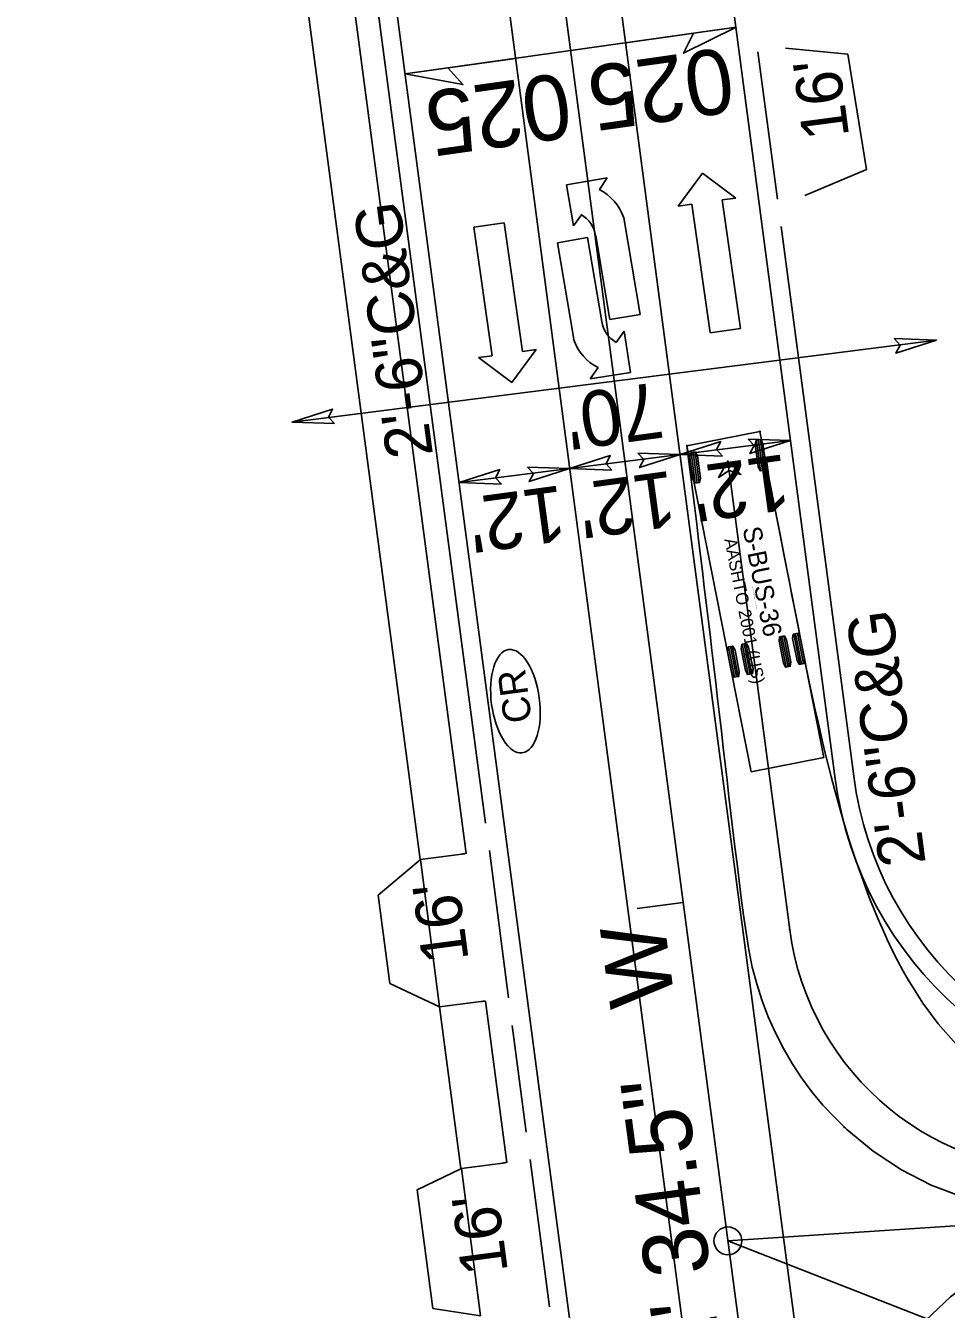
# Model space of a CAD drawing. Extents: x 2367848 to 2369479, y 800728 to 808616.
# Drawn here: x 2368550.2 to 2368649.4, y 806072.5 to 806210.8 of the extents above; entities that cross this region are included whole.
import ezdxf

# ---------------------------------------------------------------- set-up
doc = ezdxf.new("R2010")
doc.units = 0
for name, color, linetype in [('Prop AutoTurn Projected Path', 7, 'Continuous'), ('Prop AutoTurn Simulation', 7, 'Continuous'), ('Prop Conc 2ft 6in Curb and Gutter', 7, 'Continuous'), ('Prop Conc 4in Sidewalk', 7, 'Continuous'), ('Prop Conc Drive Radius Type', 7, 'Continuous'), ('Prop Conc Driveway', 7, 'Continuous'), ('Prop Dimension', 7, 'Continuous'), ('Prop EOT', 7, 'Continuous'), ('Prop Horizontal Alignment', 7, 'Continuous'), ('Prop Horizontal Alignment Direction Label', 7, 'Continuous'), ('Prop Horizontal Alignment Station Label', 7, 'Continuous'), ('Prop Horizontal Alignment Tick Small', 7, 'Continuous'), ('Prop Lane Arrow CELL', 7, 'Continuous'), ('Prop Lane Lines', 7, 'Continuous'), ('Prop Shade Light', 7, 'Continuous'), ('Prop Superelevation  Arrow CELL', 7, 'Continuous'), ('Prop Superelevation Label', 7, 'Continuous'), ('Prop Terminator CELL', 7, 'Continuous'), ('Prop WCC CELL', 7, 'Continuous'), ('Prop WCR CELL', 7, 'Continuous')]:
    doc.layers.add(name, color=color, linetype=linetype)

# ---------------------------------------------------------------- blocks, each defined once
blk = doc.blocks.new('CR')
at = {"layer": 'Prop WCC CELL'}
blk.add_ellipse((0.02, -0.02), major_axis=(5.61, 0), ratio=0.462467, dxfattribs=at)
blk.add_text('CR', height=3, dxfattribs=at).set_placement((-2.34, -1.5))

msp = doc.modelspace()

# ---------------------------------------------------------------- linework, layer by layer
at = {"layer": 'Prop AutoTurn Projected Path'}
msp.add_line((2368632.53, 806113.4), (2368625.87, 806163.88), dxfattribs=at)
for centre, radius, start, end in [((2368662.28, 806117.33), 30, 187.5263, 273.7494), ((2368673.73, 806045.93), 32, 93.7494, 187.5296)]:
    msp.add_arc(centre, radius, start, end, dxfattribs=at)
at = {"layer": 'Prop AutoTurn Simulation'}
for p, q in [((2368629.31, 806167.1), (2368621.46, 806165.56)), ((2368636.22, 806131.97), (2368629.31, 806167.1)), ((2368621.46, 806165.56), (2368628.37, 806130.43)), ((2368621.46, 806165.56), (2368621.46, 806165.56)), ((2368628.96, 806166.17), (2368629.4, 806162.86)), ((2368629.17, 806166.19), (2368629.6, 806162.89)), ((2368629.38, 806166.22), (2368629.81, 806162.92)), ((2368621.92, 806164.83), (2368622.36, 806161.53)), ((2368622.13, 806164.86), (2368622.56, 806161.56)), ((2368622.33, 806164.89), (2368622.77, 806161.58)), ((2368631.5, 806144.97), (2368632.14, 806141.7)), ((2368631.7, 806145.01), (2368632.35, 806141.74)), ((2368631.91, 806145.05), (2368632.55, 806141.78)), ((2368632.97, 806145.26), (2368633.61, 806141.99)), ((2368633.17, 806145.3), (2368633.82, 806142.03)), ((2368633.38, 806145.34), (2368634.02, 806142.07)), ((2368625.94, 806143.88), (2368626.58, 806140.61)), ((2368626.14, 806143.92), (2368626.79, 806140.65)), ((2368626.35, 806143.96), (2368626.99, 806140.69)), ((2368627.41, 806144.17), (2368628.05, 806140.9)), ((2368627.61, 806144.21), (2368628.26, 806140.94)), ((2368627.82, 806144.25), (2368628.46, 806140.98)), ((2368628.37, 806130.43), (2368636.22, 806131.97))]:
    msp.add_line(p, q, dxfattribs=at)
for points in [[(2368645.29, 806108), (2368644.77, 806108.92), (2368644.16, 806110.07), (2368643.58, 806111.21), (2368643.03, 806112.35), (2368642.52, 806113.49), (2368642.03, 806114.62), (2368641.56, 806115.75), (2368641.11, 806116.87), (2368640.69, 806117.98), (2368640.29, 806119.09), (2368639.9, 806120.19), (2368639.53, 806121.28), (2368639.17, 806122.38), (2368638.81, 806123.52), (2368638.45, 806124.71), (2368638.09, 806125.95), (2368637.72, 806127.24), (2368637.36, 806128.56), (2368637, 806129.92), (2368636.65, 806131.3), (2368636.3, 806132.72), (2368635.96, 806134.16), (2368635.62, 806135.62), (2368635.29, 806137.1), (2368634.96, 806138.6), (2368634.64, 806140.12), (2368634.32, 806141.65), (2368634.01, 806143.19), (2368633.71, 806144.75), (2368633.4, 806146.31), (2368633.09, 806147.88), (2368632.78, 806149.45), (2368632.47, 806151.04), (2368632.16, 806152.63), (2368631.84, 806154.22), (2368631.53, 806155.82), (2368631.21, 806157.42), (2368630.9, 806159.03), (2368630.58, 806160.64), (2368630.26, 806162.25), (2368629.94, 806163.86), (2368629.63, 806165.48), (2368629.31, 806167.1)], [(2368638.43, 806092.11), (2368637.38, 806093.15), (2368636.12, 806094.51), (2368634.93, 806095.94), (2368633.82, 806097.44), (2368632.8, 806098.99), (2368631.85, 806100.61), (2368630.99, 806102.28), (2368630.23, 806104), (2368629.55, 806105.75), (2368628.98, 806107.55), (2368628.5, 806109.38), (2368628.12, 806111.23), (2368627.83, 806113.1), (2368627.57, 806114.97), (2368627.32, 806116.83), (2368627.09, 806118.67), (2368626.86, 806120.5), (2368626.63, 806122.32), (2368626.41, 806124.14), (2368626.2, 806125.94), (2368625.99, 806127.73), (2368625.78, 806129.51), (2368625.58, 806131.28), (2368625.37, 806133.04), (2368625.17, 806134.8), (2368624.96, 806136.54), (2368624.76, 806138.29), (2368624.56, 806140.02), (2368624.35, 806141.75), (2368624.15, 806143.48), (2368623.95, 806145.2), (2368623.74, 806146.91), (2368623.54, 806148.62), (2368623.33, 806150.33), (2368623.13, 806152.03), (2368622.92, 806153.73), (2368622.71, 806155.43), (2368622.51, 806157.12), (2368622.3, 806158.81), (2368622.09, 806160.5), (2368621.88, 806162.19), (2368621.67, 806163.87), (2368621.46, 806165.56)], [(2368650.43, 806101.09), (2368648.52, 806103.25), (2368646.87, 806105.49), (2368645.43, 806107.78), (2368645.29, 806108)], [(2368651.12, 806084.62), (2368647.79, 806085.88), (2368644.58, 806087.52), (2368641.53, 806089.52), (2368638.7, 806091.86), (2368638.43, 806092.11)], [(2368647.18, 806071.28), (2368649.86, 806073.83), (2368652.8, 806076.09), (2368655.96, 806078.06), (2368659.32, 806079.7), (2368662.84, 806080.99), (2368666.48, 806081.91), (2368668.71, 806082.29)]]:
    msp.add_lwpolyline(points, dxfattribs=at)
for points in [[(2368628.91, 806166.16), (2368629.43, 806166.23), (2368629.64, 806165.79), (2368629.96, 806163.41), (2368629.86, 806162.92), (2368629.35, 806162.85), (2368629.13, 806163.3), (2368628.82, 806165.68)], [(2368621.87, 806164.83), (2368622.38, 806164.9), (2368622.6, 806164.45), (2368622.92, 806162.07), (2368622.82, 806161.59), (2368622.31, 806161.52), (2368622.09, 806161.96), (2368621.77, 806164.34)], [(2368625.87, 806163.88), (2368624.87, 806162.14), (2368626, 806162.88), (2368627.28, 806162.46)], [(2368631.45, 806144.96), (2368631.96, 806145.06), (2368632.2, 806144.64), (2368632.66, 806142.28), (2368632.6, 806141.79), (2368632.09, 806141.69), (2368631.85, 806142.12), (2368631.38, 806144.48)], [(2368632.92, 806145.25), (2368633.43, 806145.35), (2368633.67, 806144.93), (2368634.14, 806142.57), (2368634.07, 806142.08), (2368633.56, 806141.98), (2368633.32, 806142.41), (2368632.85, 806144.77)], [(2368625.89, 806143.87), (2368626.4, 806143.97), (2368626.64, 806143.54), (2368627.1, 806141.19), (2368627.04, 806140.7), (2368626.53, 806140.6), (2368626.29, 806141.03), (2368625.82, 806143.38)], [(2368627.36, 806144.16), (2368627.87, 806144.26), (2368628.11, 806143.83), (2368628.58, 806141.48), (2368628.51, 806140.99), (2368628, 806140.89), (2368627.76, 806141.32), (2368627.29, 806143.67)]]:
    msp.add_lwpolyline(points, close=True, dxfattribs=at)
for centre in [(2368629.31, 806167.1), (2368621.46, 806165.56), (2368625.87, 806163.88), (2368632.53, 806113.4), (2368632.53, 806113.4), (2368645.29, 806108), (2368645.29, 806108), (2368638.43, 806092.11), (2368638.43, 806092.11)]:
    msp.add_circle(centre, 0.0417, dxfattribs=at)
at = {"layer": 'Prop Conc 2ft 6in Curb and Gutter'}
for p, q in [((2368599.75, 806124.89), (2368582.79, 806253.21)), ((2368639.43, 806129.93), (2368631.6, 806189.19)), ((2368604.15, 806091.59), (2368602.63, 806103.08))]:
    msp.add_line(p, q, dxfattribs=at)
msp.add_arc((2368677.1, 806134.91), 38, 187.5263, 269.9974, dxfattribs=at)
at = {"layer": 'Prop Conc 4in Sidewalk'}
for p, q in [((2368597.66, 806121.63), (2368579.93, 806255.81)), ((2368592.7, 806120.96), (2368574.97, 806255.2)), ((2368597.1, 806087.65), (2368594.8, 806105.09)), ((2368602.06, 806088.33), (2368599.76, 806105.69))]:
    msp.add_line(p, q, dxfattribs=at)
for centre, radius, start, end in [((2368596.82, 806124.52), 3, 277.425, 286.2491), ((2368599.64, 806102.68), 3.01, 87.5978, 97.1636), ((2368601.22, 806091.22), 3, 277.4254, 286.1541)]:
    msp.add_arc(centre, radius, start, end, dxfattribs=at)
at = {"layer": 'Prop Conc Drive Radius Type'}
for p, q in [((2368629.11, 806208), (2368631.21, 806192.14)), ((2368602.24, 806106.06), (2368600.18, 806121.92)), ((2368606.64, 806072.76), (2368604.58, 806088.62))]:
    msp.add_line(p, q, dxfattribs=at)
at = {"layer": 'Prop Conc Driveway'}
for p, q in [((2368592.74, 806120.96), (2368597.2, 806121.54)), ((2368588.19, 806117.14), (2368592.74, 806120.96)), ((2368594.8, 806105.09), (2368592.74, 806120.96)), ((2368589.43, 806107.62), (2368588.19, 806117.14)), ((2368594.8, 806105.09), (2368589.43, 806107.62)), ((2368594.8, 806105.09), (2368599.26, 806105.67)), ((2368601.61, 806088.24), (2368597.15, 806087.66)), ((2368597.15, 806087.66), (2368592.4, 806085.38)), ((2368599.2, 806071.79), (2368597.15, 806087.66)), ((2368594.06, 806072.59), (2368592.4, 806085.38)), ((2368599.2, 806071.79), (2368594.06, 806072.59))]:
    msp.add_line(p, q, dxfattribs=at)
at = {"layer": 'Prop Dimension'}
for p, q in [((2368578.91, 806168.11), (2368648.35, 806176.94)), ((2368596.92, 806161.58), (2368632.63, 806166.12))]:
    msp.add_line(p, q, dxfattribs=at)
at = {"layer": 'Prop EOT'}
for p, q in [((2368613.33, 806037.35), (2368557.45, 806460.31)), ((2368637.45, 806129.67), (2368615.22, 806297.92)), ((2368638.8, 806207.75), (2368632.09, 806208.39)), ((2368640.8, 806195.31), (2368638.8, 806207.75)), ((2368634.18, 806192.53), (2368640.8, 806195.31))]:
    msp.add_line(p, q, dxfattribs=at)
msp.add_arc((2368677.1, 806134.91), 40, 187.5263, 269.9974, dxfattribs=at)
at = {"layer": 'Prop Horizontal Alignment'}
for p, q in [((2368631.17, 806039.71), (2368556.15, 806607.59)), ((2368625.87, 806079.87), (2368847.64, 806094.4))]:
    msp.add_line(p, q, dxfattribs=at)
at = {"layer": 'Prop Horizontal Alignment Station Label'}
msp.add_line((2368625.87, 806079.87), (2368713.66, 806045.49), dxfattribs=at)
msp.add_circle((2368625.87, 806079.87), 1.5, dxfattribs=at)
at = {"layer": 'Prop Horizontal Alignment Tick Small'}
msp.add_line((2368621.05, 806116.34), (2368616.09, 806115.69), dxfattribs=at)
at = {"layer": 'Prop Lane Arrow CELL'}
for p, q in [((2368620.51, 806191.37), (2368623.14, 806194.93)), ((2368623.14, 806194.93), (2368626.74, 806192.25)), ((2368612.87, 806194.42), (2368608.48, 806193.68)), ((2368608.48, 806193.68), (2368609.23, 806189.24)), ((2368612.02, 806193.16), (2368612.87, 806194.42)), ((2368626.74, 806192.25), (2368625.26, 806192.04)), ((2368625.26, 806192.04), (2368627.22, 806178.18)), ((2368609.23, 806189.24), (2368610.09, 806190.45)), ((2368621.99, 806191.58), (2368620.51, 806191.37)), ((2368623.95, 806177.72), (2368621.99, 806191.58)), ((2368598.51, 806189.12), (2368601.78, 806189.58)), ((2368600.46, 806175.26), (2368598.51, 806189.12)), ((2368601.78, 806189.58), (2368603.73, 806175.72)), ((2368616.41, 806179.7), (2368614.66, 806190.11)), ((2368610.76, 806187.98), (2368607.51, 806187.43)), ((2368612.28, 806178.95), (2368610.76, 806187.98)), ((2368611.64, 806188.18), (2368613.16, 806179.15)), ((2368607.51, 806187.43), (2368609.26, 806177.03)), ((2368613.16, 806179.15), (2368616.41, 806179.7)), ((2368627.22, 806178.18), (2368623.95, 806177.72)), ((2368614.69, 806177.89), (2368613.83, 806176.68)), ((2368615.39, 806173.44), (2368614.69, 806177.89)), ((2368598.98, 806175.05), (2368600.46, 806175.26)), ((2368605.22, 806175.93), (2368602.59, 806172.37)), ((2368603.73, 806175.72), (2368605.22, 806175.93)), ((2368602.59, 806172.37), (2368598.98, 806175.05)), ((2368611.9, 806173.97), (2368611.04, 806172.76)), ((2368611.04, 806172.76), (2368615.39, 806173.44))]:
    msp.add_line(p, q, dxfattribs=at)
for centre, radius, start, end in [((2368609.66, 806188.47), 5.25, 18.2406, 63.5523), ((2368608.39, 806187.65), 3.27, 9.5645, 59.2227), ((2368615.5, 806179.49), 3.27, 189.5645, 239.2227), ((2368614.23, 806178.67), 5.25, 198.2406, 243.5523)]:
    msp.add_arc(centre, radius, start, end, dxfattribs=at)
at = {"layer": 'Prop Lane Lines'}
for p, q in [((2368637.12, 806040.49), (2368562.1, 806608.37)), ((2368625.23, 806038.92), (2368550.2, 806606.8))]:
    msp.add_line(p, q, dxfattribs=at)
at = {"layer": 'Prop Shade Light'}
for p, q in [((2368597.66, 806121.63), (2368579.93, 806255.81)), ((2368574.97, 806255.2), (2368592.7, 806120.96)), ((2368592.74, 806120.96), (2368597.2, 806121.54)), ((2368592.72, 806120.94), (2368592.74, 806120.96)), ((2368599.26, 806105.67), (2368594.8, 806105.09)), ((2368594.8, 806105.09), (2368597.1, 806087.65)), ((2368602.06, 806088.33), (2368599.76, 806105.69)), ((2368597.15, 806087.66), (2368601.61, 806088.24)), ((2368597.11, 806087.64), (2368597.15, 806087.66))]:
    msp.add_line(p, q, dxfattribs=at)
for points in [[(2368592.7, 806120.96), (2368592.72, 806120.94)], [(2368597.1, 806087.65), (2368597.11, 806087.64)]]:
    msp.add_lwpolyline(points, dxfattribs=at)
for centre, radius, start, end in [((2368596.82, 806124.52), 3, 277.425, 286.2491), ((2368599.64, 806102.68), 3.01, 87.5978, 97.1636), ((2368601.22, 806091.22), 3, 277.4254, 286.1541)]:
    msp.add_arc(centre, radius, start, end, dxfattribs=at)
at = {"layer": 'Prop Superelevation  Arrow CELL'}
for p, q in [((2368626.76, 806210.67), (2368614.88, 806208.99)), ((2368591.1, 806205.62), (2368602.98, 806207.3))]:
    msp.add_line(p, q, dxfattribs=at)
for points in [[(2368626.76, 806210.67), (2368621.1, 806207.85), (2368622.18, 806210.02)], [(2368591.1, 806205.62), (2368597.32, 806204.48), (2368595.68, 806206.27)]]:
    msp.add_lwpolyline(points, close=True, dxfattribs=at)
at = {"layer": 'Prop Superelevation Label'}
msp.add_line((2368591.1, 806205.62), (2368626.76, 806210.67), dxfattribs=at)
at = {"layer": 'Prop Terminator CELL'}
for points in [[(2368643.78, 806177.1), (2368648.35, 806176.94), (2368643.97, 806175.54), (2368644.43, 806176.41)], [(2368583.47, 806167.95), (2368578.91, 806168.11), (2368583.28, 806169.51), (2368582.82, 806168.64)], [(2368625.29, 806164.44), (2368620.73, 806164.6), (2368625.1, 806166.01), (2368624.64, 806165.14)], [(2368628.07, 806166.28), (2368632.63, 806166.12), (2368628.25, 806164.71), (2368628.72, 806165.58)], [(2368613.38, 806162.93), (2368608.82, 806163.09), (2368613.2, 806164.49), (2368612.74, 806163.62)], [(2368616.16, 806164.76), (2368620.73, 806164.6), (2368616.35, 806163.2), (2368616.81, 806164.07)], [(2368601.48, 806161.42), (2368596.92, 806161.58), (2368601.29, 806162.98), (2368600.83, 806162.11)], [(2368604.26, 806163.25), (2368608.82, 806163.09), (2368604.45, 806161.69), (2368604.91, 806162.56)]]:
    msp.add_lwpolyline(points, close=True, dxfattribs=at)

# ---------------------------------------------------------------- block references
at = {"layer": 'Prop WCR CELL', "rotation": 97.54241161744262}
msp.add_blockref('CR', (2368602.96, 806138), dxfattribs=at)

# ---------------------------------------------------------------- texts
at = {"layer": 'Prop AutoTurn Simulation'}
for s, height, p in [('S-BUS-36', 2, (2368627.45, 806156.65)), ('AASHTO 2001 (US)', 1.3333, (2368625.48, 806155.46)), ('(c) 2014 Transoft Solutions, Inc. All rights reserved.', 0.08, (2368628.49, 806150.36))]:
    msp.add_text(s, height=height, rotation=281.1349, dxfattribs=at).set_placement(p)
at = {"layer": 'Prop Dimension'}
for s, height, rotation, p in [("16'", 5, 97.5263, (2368638.95, 806198.88)), ('2\'-6"C&G', 5, 97.5241, (2368594.1, 806164.56)), ("70'", 6, 187.7641, (2368618.41, 806172.43)), ("12'", 6, 187.7641, (2368632.07, 806164.67)), ("12'", 6, 187.7641, (2368619.79, 806162.88)), ("12'", 6, 187.7641, (2368607.93, 806161.32)), ('2\'-6"C&G', 5, 97.5241, (2368647.2, 806120.56)), ("16'", 5, 97.5263, (2368597.95, 806110.13)), ("16'", 5, 97.5263, (2368602.18, 806076.54))]:
    msp.add_text(s, height=height, rotation=rotation, dxfattribs=at).set_placement(p)
at = {"layer": 'Prop Horizontal Alignment Direction Label'}
msp.add_text('N 7%%d 31\' 34.5"   W', height=7, rotation=97.5263, dxfattribs=at).set_placement((2368628.69, 806041.13))
at = {"layer": 'Prop Superelevation Label'}
for p in [(2368625.91, 806208.53), (2368608.4, 806205.79)]:
    msp.add_text('025', height=7, rotation=188.0589, dxfattribs=at).set_placement(p)

doc.saveas('drawing.dxf')
